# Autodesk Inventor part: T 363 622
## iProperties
Created: 2006-06
Part Number: T 363 622
Material: 1.0330.5
Document SubType Name: Sheet Metal
Designer: I.Baliuc
Manufacturer: Standard
Standards Organization: Custom
Description: Seitenblech, rechts
Density: 7.84 g/cm^3
Sheet Metal Rule: Standard
Title: Seitenblech, rechts
Company: Mayer & Müller AG Schaltgeräte
HalbzeugNorm: DIN 1544
Zweck: Vorkontakt HSLT
Author: T.Messerschmitt
Keywords: 363030
Revision Number: 363622
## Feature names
1. Extrusion1
2. Bohrung_Ø8.5_01 [Hole]
3. Bohrung_Ø8.5_02 [Hole]
4. Bohrung_Ø8.5_03 [Hole]
5. Bohrung_Ø8.5_04 [Hole]
6. Bohrung1 [Hole]
7. Bohrung_Ø24 [Hole]
8. Bezeichnung3 [Tagging]
9. Ausschneiden1
10. Ausschneiden2
11. Ausschneiden3
